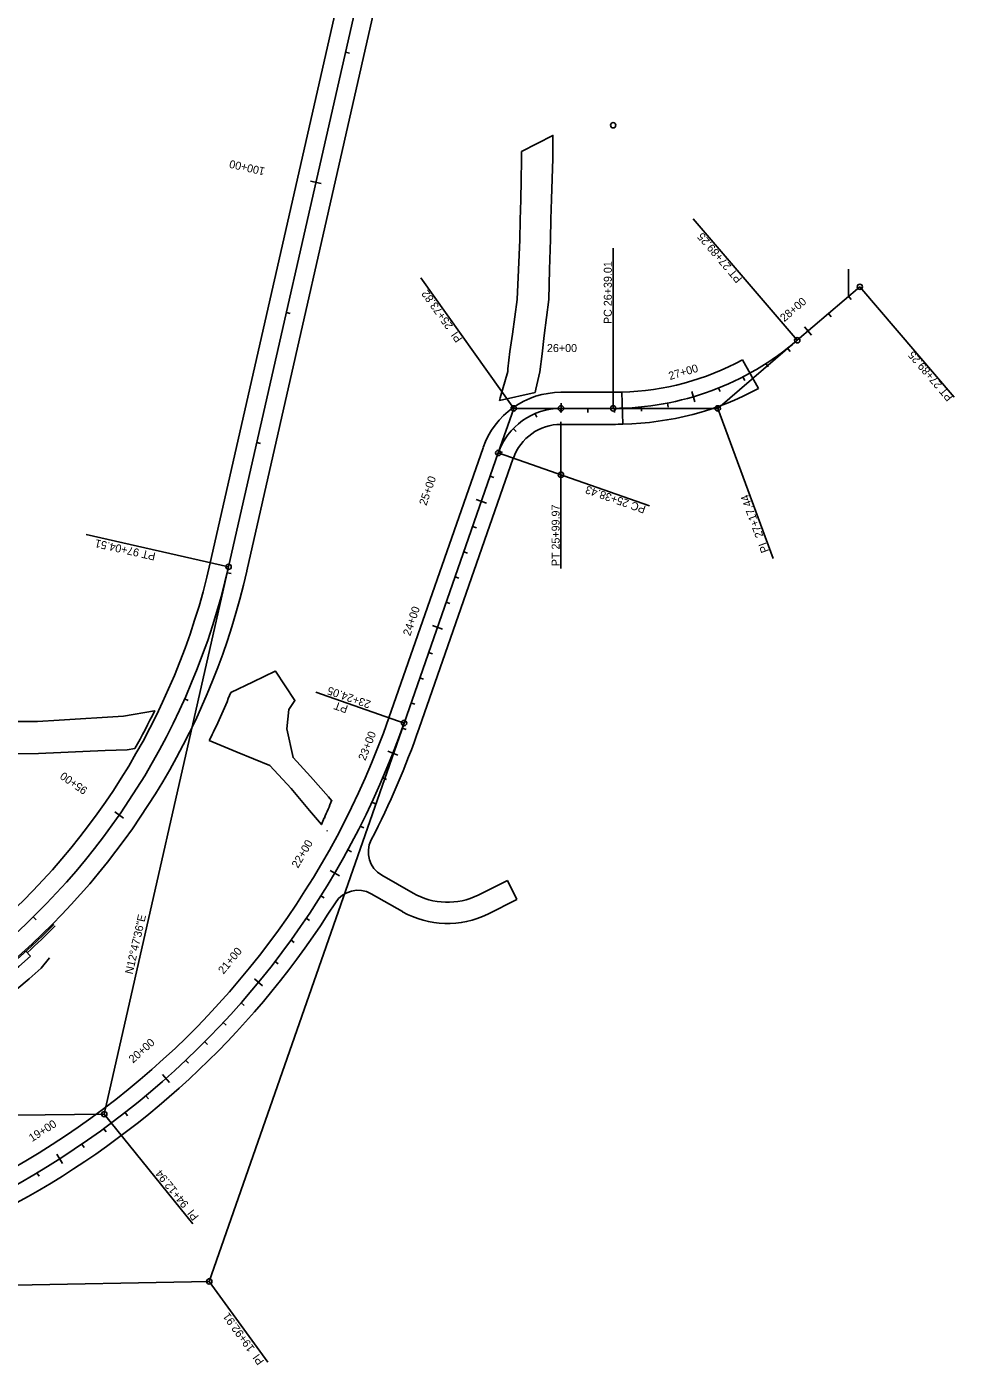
# Model space of a CAD drawing. Extents: x 1710755 to 1712791, y 548830 to 551199.
# Drawn here: x 1712096 to 1712791, y 549029 to 550032 of the extents above; entities that cross this region are included whole.
import ezdxf

# ---------------------------------------------------------------- set-up
doc = ezdxf.new("R2010")
doc.units = 0
for name, color, linetype in [('R_Concrete', 7, 'Continuous'), ('R_Draft', 7, 'Continuous'), ('R_Horz Alg', 7, 'Continuous'), ('R_Horz Alg Annot', 7, 'Continuous'), ('R_Proposed Road_Lane', 7, 'Continuous')]:
    doc.layers.add(name, color=color, linetype=linetype)

msp = doc.modelspace()

# ---------------------------------------------------------------- linework, layer by layer
at = {"layer": 'R_Concrete'}
for p, q in [((1712711.5, 549830.1), (1712711.5, 549850.3)), ((1712098.3, 549335.5), (1712094.9, 549339.2)), ((1712106.3, 549326.6), (1712112.7, 549334.3))]:
    msp.add_line(p, q, dxfattribs=at)
for radius, start, end in [(548, 276.455, 315.2153), (549.4, 312.1709, 315.2153), (553, 274.3371, 312.1708), (565, 273.1321, 312.1704)]:
    msp.add_arc((1711727, 549745.3), radius, start, end, dxfattribs=at)
at = {"layer": 'R_Draft'}
for p, q in [((1712466.4, 549938.5), (1712489.9, 549950.6)), ((1712643.9, 549760.9), (1712631.9, 549782.5)), ((1712320.7, 549429.1), (1712320.7, 549429.6))]:
    msp.add_line(p, q, dxfattribs=at)
for points in [[(1712489.9, 549950.6), (1712489.9, 549950.6), (1712489.9, 549950.6), (1712489.9, 549950.6), (1712489.9, 549950.6), (1712489.9, 549950.6), (1712489.9, 549948.5), (1712489.7, 549933.4), (1712489.3, 549918.2), (1712488.9, 549903), (1712488.4, 549887.9), (1712488, 549872.7), (1712487.4, 549850.2), (1712486.8, 549827.8), (1712485.1, 549814.2), (1712483.4, 549800.6), (1712481.7, 549787), (1712480, 549773.4), (1712477.1, 549760.5), (1712476.5, 549758)], [(1712449.8, 549752), (1712450.4, 549754), (1712456.2, 549773.8), (1712456, 549775.6), (1712457.7, 549788.6), (1712459.5, 549801.6), (1712461.3, 549814.6), (1712463, 549827.6), (1712464.1, 549850), (1712465.1, 549872.4), (1712465.4, 549887.3), (1712465.7, 549902.3), (1712466, 549917.2), (1712466.3, 549932.2), (1712466.4, 549938.6), (1712466.4, 549938.5), (1712466.4, 549938.6), (1712466.4, 549938.6), (1712466.4, 549938.5)], [(1712476.5, 549758), (1712449.8, 549752)], [(1712282, 549549.2), (1712281.7, 549549), (1712265.1, 549541), (1712248.5, 549533.1), (1712248.5, 549533.1)], [(1712292, 549520.4), (1712296.5, 549527.2), (1712282, 549549.2)], [(1712078.8, 549511.4), (1712103.7, 549511.4), (1712119.8, 549512.4), (1712135.9, 549513.4), (1712152, 549514.4), (1712168.1, 549515.4), (1712191.4, 549519.5)], [(1712324, 549452.3), (1712321.8, 549454.8), (1712308.1, 549470.1), (1712295.1, 549484.4), (1712290.5, 549506), (1712292, 549520.4)], [(1712232.3, 549497.1), (1712241.2, 549493.4), (1712253.3, 549488.4), (1712265.4, 549483.4), (1712277.6, 549478.4), (1712293.7, 549461.2), (1712307.5, 549444.7), (1712316.5, 549434.1), (1712318.5, 549439.1)], [(1712176.6, 549491.2), (1712170.8, 549490.2), (1712154.2, 549489.6), (1712137.6, 549488.9), (1712121, 549488.2), (1712104.4, 549487.5), (1712079.7, 549487.2)]]:
    msp.add_lwpolyline(points, dxfattribs=at)
for centre, radius, start, end in [((1712536.1, 549958.6), 200.5, 271.5708, 298.5708), ((1712537.6, 549959), 224.8, 271.2207, 298.2207), ((1711727, 549745.3), 563, 333.8405, 337.855), ((1711727, 549745.3), 516.4, 330.5199, 334.0724), ((1711895.9, 549621), 460.2, 336.7051, 338.4954)]:
    msp.add_arc(centre, radius, start, end, dxfattribs=at)
at = {"layer": 'R_Horz Alg'}
for p, q in [((1712450.8, 550525.8), (1712246.8, 549627.3)), ((1712246.8, 549627.3), (1712450.8, 550525.8)), ((1712673, 549797.1), (1712719.9, 549837.2)), ((1712495.9, 549746.1), (1712535, 549746.1)), ((1712378.3, 549510.2), (1712448.9, 549712.7))]:
    msp.add_line(p, q, dxfattribs=at)
for centre, radius, start, end in [((1712535, 549958.3), 212.2, 270, 310.5648), ((1712495.9, 549696.3), 49.8, 90, 160.7734), ((1711727, 549745.3), 533, 270.6428, 347.2066), ((1711727, 549745.3), 533, 270.6428, 347.2066), ((1711777.2, 549719.9), 636.6, 271.0787, 340.7734)]:
    msp.add_arc(centre, radius, start, end, dxfattribs=at)
at = {"layer": 'R_Horz Alg Annot'}
for p, q in [((1712613.4, 549746.1), (1712673, 549797.1)), ((1712448.9, 549712.7), (1712460.5, 549746.1)), ((1712460.5, 549746.1), (1712495.9, 549746.1)), ((1712535, 549746.1), (1712613.4, 549746.1)), ((1712232.3, 549091.7), (1712378.3, 549510.2)), ((1711789.2, 549083.4), (1712232.3, 549091.7))]:
    msp.add_line(p, q, dxfattribs=at)
for points in [[(1712337.3, 550012.3), (1712334.3, 550013)], [(1712308.3, 549916.3), (1712316.1, 549914.5)], [(1712673, 549797.1), (1712594.9, 549888.2)], [(1712535, 549746.1), (1712535, 549866.1)], [(1712460.5, 549746.1), (1712391, 549843.9)], [(1712790.6, 549754.6), (1712719.9, 549837.2)], [(1712713.5, 549827.8), (1712711.5, 549830.1)], [(1712293, 549817.3), (1712290.1, 549817.9)], [(1712698.3, 549814.8), (1712696.3, 549817.1)], [(1712678.5, 549807.1), (1712683.7, 549801)], [(1712667.7, 549788.8), (1712665.8, 549791.2)], [(1712651.1, 549777.1), (1712649.5, 549779.6)], [(1712633.6, 549767), (1712632.2, 549769.7)], [(1712594, 549758.6), (1712596.3, 549750.9)], [(1712615.1, 549758.6), (1712614, 549761.3)], [(1712495.9, 549746.1), (1712495.9, 549743.1)], [(1712496, 549750.1), (1712496, 549743)], [(1712516, 549743.1), (1712516, 549746.1)], [(1712536, 549743.1), (1712536, 549746.1)], [(1712556.2, 549744.1), (1712555.9, 549747.1)], [(1712576.3, 549747.1), (1712575.7, 549750)], [(1712613.4, 549746.1), (1712655, 549633.5)], [(1712477.7, 549739.4), (1712476.5, 549742.1)], [(1712495.9, 549735.9), (1712495.9, 549626.1)], [(1712462.3, 549728.8), (1712460.1, 549730.9)], [(1712270.8, 549719.7), (1712267.9, 549720.4)], [(1712452.2, 549713.1), (1712449.4, 549714.1)], [(1712448.9, 549712.7), (1712562.2, 549673.1)], [(1712445.6, 549694.3), (1712442.8, 549695.3)], [(1712432.4, 549677.7), (1712440, 549675.1)], [(1712432.5, 549656.5), (1712429.6, 549657.5)], [(1712246.8, 549627.3), (1712140.1, 549651.5)], [(1712425.9, 549637.6), (1712423.1, 549638.6)], [(1711733, 549212.4), (1712153.6, 549217.1), (1712246.8, 549627.3)], [(1712248.7, 549622.2), (1712245.8, 549622.9)], [(1712419.3, 549618.7), (1712416.5, 549619.7)], [(1712412.7, 549599.8), (1712409.9, 549600.8)], [(1712399.5, 549583.3), (1712407.1, 549580.6)], [(1712399.5, 549562.1), (1712396.7, 549563.1)], [(1712393, 549543.2), (1712390.1, 549544.2)], [(1712216.6, 549527.1), (1712213.8, 549528.3)], [(1712378.3, 549510.2), (1712312.1, 549533.3)], [(1712386.4, 549524.3), (1712383.5, 549525.3)], [(1712379.8, 549505.4), (1712376.9, 549506.4)], [(1712366.2, 549489.1), (1712373.7, 549486.2)], [(1712365.1, 549468), (1712362.4, 549469.2)], [(1712161.5, 549443.6), (1712168.1, 549439)], [(1712356.9, 549449.7), (1712354.2, 549450.9)], [(1712348.1, 549431.6), (1712345.5, 549432.9)], [(1712338.8, 549413.8), (1712336.2, 549415.2)], [(1712322.9, 549399.8), (1712329.8, 549395.8)], [(1712318.5, 549379.1), (1712315.9, 549380.7)], [(1712102.5, 549362.8), (1712100.4, 549365)], [(1712307.5, 549362.3), (1712305, 549364)], [(1712296, 549345.8), (1712293.6, 549347.6)], [(1712284, 549329.7), (1712281.6, 549331.5)], [(1712266.1, 549318.4), (1712272.3, 549313.3)], [(1712258.5, 549298.6), (1712256.2, 549300.6)], [(1712245, 549283.7), (1712242.8, 549285.8)], [(1712231.1, 549269.3), (1712229, 549271.4)], [(1712216.7, 549255.2), (1712214.7, 549257.4)], [(1712197.3, 549246.9), (1712202.6, 549240.9)], [(1712186.7, 549228.5), (1712184.8, 549230.8)], [(1712153.6, 549217.1), (1712219.9, 549135)], [(1712171, 549215.9), (1712169.2, 549218.3)], [(1712155, 549203.8), (1712153.2, 549206.2)], [(1712138.6, 549192.2), (1712136.9, 549194.7)], [(1712118.1, 549187), (1712122.4, 549180.2)], [(1712104.8, 549170.5), (1712103.2, 549173.1)], [(1712232.3, 549091.7), (1712276.1, 549031.3)]]:
    msp.add_lwpolyline(points, dxfattribs=at)
for centre in [(1712535, 549958.3), (1712719.9, 549837.2), (1712673, 549797.1), (1712460.5, 549746.1), (1712495.9, 549746.1), (1712535, 549746.1), (1712613.4, 549746.1), (1712448.9, 549712.7), (1712495.9, 549696.3), (1712246.8, 549627.3), (1712246.8, 549627.3), (1712378.3, 549510.2), (1712153.6, 549217.1), (1712232.3, 549091.7)]:
    msp.add_circle(centre, 2, dxfattribs=at)
at = {"layer": 'R_Proposed Road_Lane'}
for p, q in [((1712233.1, 549630.4), (1712437.2, 550528.9)), ((1712260.4, 549624.2), (1712464.5, 550522.7)), ((1712495.9, 549758.1), (1712535, 549758.1)), ((1712541.6, 549758.2), (1712542.3, 549734.2)), ((1712541.6, 549758.2), (1712542.3, 549734.2)), ((1712495.9, 549734.1), (1712535, 549734.1)), ((1712367, 549514.2), (1712437.6, 549716.6)), ((1712389.6, 549506.3), (1712460.2, 549708.7)), ((1712385.1, 549382.8), (1712361.6, 549396.1)), ((1712455.8, 549392.2), (1712433.9, 549381.3)), ((1712462.9, 549377.9), (1712455.8, 549392.2)), ((1712377.1, 549368.9), (1712353.7, 549382.2)), ((1712462.9, 549377.9), (1712441, 549367))]:
    msp.add_line(p, q, dxfattribs=at)
for centre, radius, start, end in [((1712495.9, 549696.3), 61.8, 90, 160.7734), ((1712535, 549958.3), 200.2, 270, 271.8863), ((1712495.9, 549696.3), 37.8, 90, 160.7734), ((1712535, 549958.3), 224.2, 270, 271.8863), ((1711727, 549745.3), 519, 270.6428, 347.2066), ((1711727, 549745.3), 547, 276.4562, 347.2066), ((1711777.2, 549719.9), 624.6, 271.0787, 340.7734), ((1711777.2, 549719.9), 648.6, 332.7289, 340.7734), ((1712371.5, 549413.5), 20, 152.7289, 240.3288), ((1712343.8, 549364.9), 20, 60.3288, 147.9287), ((1711777.2, 549719.9), 648.6, 271.0787, 327.9287), ((1712410.8, 549427.9), 52, 240.3288, 296.3424), ((1712410.8, 549427.9), 68, 240.3288, 296.3424)]:
    msp.add_arc(centre, radius, start, end, dxfattribs=at)

# ---------------------------------------------------------------- texts
at = {"layer": 'R_Horz Alg Annot'}
for s, rotation, p in [('100+00', 167.2066, (1712274.5, 549926.4)), ('PT 27+89.25', 130.5648, (1712632.1, 549843.3)), ('PC 26+39.01', 90, (1712534, 549809.3)), ('PI  25+73.82', 125.3867, (1712422.3, 549798.2)), ('28+00', 40.5648, (1712663.3, 549810.6)), ('PT 27+89.25', 130.5648, (1712790.1, 549754.6)), ('27+00', 16.4663, (1712577.6, 549767.3)), ('25+00', 70.7734, (1712395, 549672.8)), ('PC 25+38.43', 160.7734, (1712560, 549672.8)), ('PI  27+17.44', 110.2824, (1712651.9, 549639.1)), ('PT 25+99.97', 90, (1712494.9, 549627.8)), ('PT 97+04.51', 167.2066, (1712192.5, 549637.8)), ('24+00', 70.7734, (1712382.9, 549575.1)), ('23+24.05', 160.7734, (1712353.9, 549526.6)), ('PT', 160.7734, (1712336.8, 549523.1)), ('23+00', 68.6088, (1712349.3, 549481.6)), ('95+00', 145.2214, (1712141.7, 549461.1)), ('22+00', 59.6088, (1712298.8, 549401)), ('N12%%d47\'36"E', 77.2066, (1712174.9, 549321.6)), ('21+00', 50.6088, (1712243, 549321.6)), ('20+00', 41.6088, (1712175.2, 549255)), ('19+00', 32.6088, (1712099.5, 549196.1)), ('PI  94+12.94', 128.9247, (1712224.8, 549140.4)), ('PI  19+92.91', 125.926, (1712273.7, 549031.9))]:
    msp.add_text(s, height=6, rotation=rotation, dxfattribs=at).set_placement(p)
msp.add_text('26+00', height=6, dxfattribs=at).set_placement((1712485.4, 549788.3))

doc.saveas('drawing.dxf')
